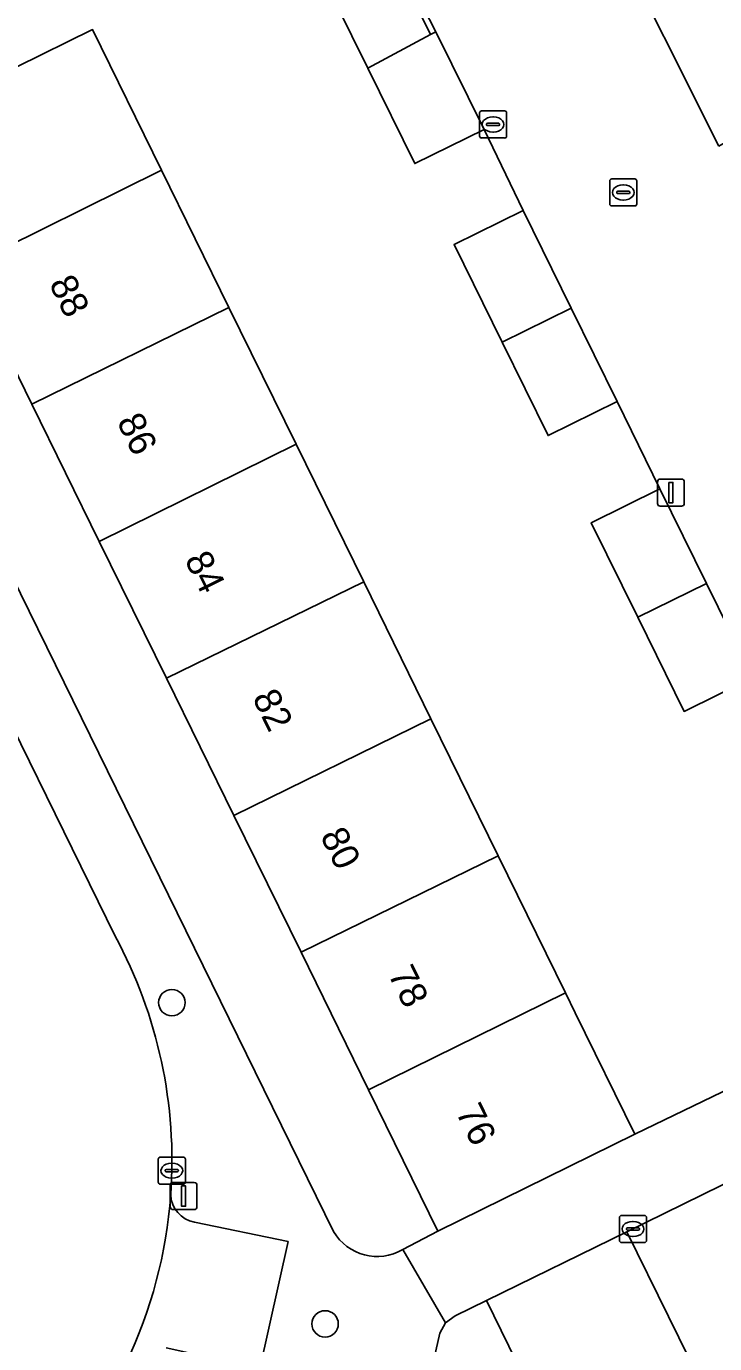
# Model space of a CAD drawing. Extents: x 159716 to 160783, y 383290 to 384031.
# Drawn here: x 160086.41 to 160111.85, y 383383.96 to 383432.64 of the extents above; entities that cross this region are included whole.
import ezdxf

# ---------------------------------------------------------------- set-up
doc = ezdxf.new("R2010")
doc.units = 0
for name, color, linetype in [('IMGEO_Boom', 7, 'Continuous'), ('IMGEO_Erf', 7, 'Continuous'), ('IMGEO_Kolk', 7, 'Continuous'), ('IMGEO_Lichtmast', 7, 'Continuous'), ('IMGEO_Pand', 7, 'Continuous'), ('IMGEO_Pand_nummerreeks', 7, 'Continuous'), ('IMGEO_Parkeervlak_open', 7, 'Continuous'), ('IMGEO_Rijbaan_lokaal_open', 7, 'Continuous'), ('IMGEO_Voetpad_open', 7, 'Continuous')]:
    doc.layers.add(name, color=color, linetype=linetype)

msp = doc.modelspace()

# ---------------------------------------------------------------- linework, layer by layer
at = {"layer": 'IMGEO_Boom'}
for centre in [(160091.79, 383396.564), (160097.452, 383384.694)]:
    msp.add_circle(centre, 0.489, dxfattribs=at)
at = {"layer": 'IMGEO_Erf'}
for points in [[(160099.795, 383435.475), (160101.344, 383432.33), (160101.55, 383432.432), (160099.933, 383435.581)], [(160103.996, 383420.964), (160102.218, 383424.571), (160104.772, 383425.829), (160103.329, 383428.824), (160100.768, 383427.562), (160099.034, 383431.087), (160097.261, 383434.69)], [(160100.324, 383387.443), (160101.622, 383388.127), (160099.062, 383393.337), (160096.563, 383398.425), (160094.082, 383403.475), (160091.588, 383408.552), (160089.107, 383413.603), (160086.617, 383418.672), (160084.135, 383423.723), (160081.575, 383428.935), (160086.063, 383431.14), (160088.858, 383432.513), (160091.41, 383427.319), (160093.9, 383422.25), (160096.381, 383417.199), (160098.879, 383412.113), (160101.365, 383407.053), (160103.85, 383401.994), (160106.34, 383396.925), (160106.7, 383396.193), (160108.905, 383391.705), (160116.095, 383395.177)], [(160080.405, 383423.453), (160097.768, 383388.109)], [(160113.264, 383408.578), (160110.723, 383407.326), (160109.007, 383410.807), (160107.289, 383414.292), (160109.83, 383415.544), (160108.251, 383418.772), (160105.697, 383417.513), (160103.996, 383420.964)], [(160106.151, 383379.966), (160103.414, 383385.561), (160102.265, 383384.994), (160101.907, 383384.734), (160101.689, 383384.35), (160090.51, 383335.068)]]:
    msp.add_lwpolyline(points, dxfattribs=at)
msp.add_lwpolyline([(160120.499, 383393.934), (160108.611, 383388.092), (160111.681, 383381.843), (160115.082, 383383.587), (160123.539, 383387.742)], close=True, dxfattribs=at)
msp.add_arc((160099.379, 383389.055), 1.869, 210.4205, 300.3706, dxfattribs=at)
at = {"layer": 'IMGEO_Kolk'}
for p, q in [((160103.161, 383428.584), (160103.161, 383429.436)), ((160103.236, 383429.51), (160104.088, 383429.51)), ((160103.649, 383429.29), (160103.674, 383429.29)), ((160104.162, 383429.436), (160104.162, 383428.584)), ((160103.42, 383429.004), (160103.42, 383429.016)), ((160103.858, 383428.967), (160103.46, 383428.967)), ((160103.463, 383429.053), (160103.861, 383429.053)), ((160103.904, 383429.016), (160103.904, 383429.004)), ((160104.088, 383428.51), (160103.236, 383428.51)), ((160103.672, 383428.73), (160103.647, 383428.73)), ((160107.973, 383426.072), (160107.973, 383426.924)), ((160108.048, 383426.998), (160108.9, 383426.998)), ((160108.974, 383426.924), (160108.974, 383426.072)), ((160108.232, 383426.492), (160108.232, 383426.504)), ((160108.67, 383426.455), (160108.272, 383426.455)), ((160108.275, 383426.541), (160108.673, 383426.541)), ((160108.461, 383426.778), (160108.486, 383426.778)), ((160108.716, 383426.504), (160108.716, 383426.492)), ((160108.9, 383425.998), (160108.048, 383425.998)), ((160108.484, 383426.218), (160108.459, 383426.218)), ((160091.362, 383390.856), (160092.214, 383390.856)), ((160091.287, 383389.93), (160091.287, 383390.782)), ((160091.546, 383390.35), (160091.546, 383390.362)), ((160091.589, 383390.399), (160091.987, 383390.399)), ((160091.775, 383390.636), (160091.8, 383390.636)), ((160092.03, 383390.362), (160092.03, 383390.35)), ((160092.288, 383390.782), (160092.288, 383389.93)), ((160092.214, 383389.856), (160091.362, 383389.856)), ((160091.984, 383390.313), (160091.586, 383390.313)), ((160091.798, 383390.076), (160091.773, 383390.076)), ((160108.332, 383387.775), (160108.332, 383388.627)), ((160108.407, 383388.701), (160109.259, 383388.701)), ((160108.82, 383388.481), (160108.845, 383388.481)), ((160109.333, 383388.627), (160109.333, 383387.775)), ((160108.591, 383388.195), (160108.591, 383388.207)), ((160109.029, 383388.158), (160108.631, 383388.158)), ((160108.634, 383388.244), (160109.032, 383388.244)), ((160108.843, 383387.921), (160108.818, 383387.921)), ((160109.075, 383388.207), (160109.075, 383388.195)), ((160109.259, 383387.701), (160108.407, 383387.701))]:
    msp.add_line(p, q, dxfattribs=at)
for points in [[(160103.161, 383428.584), (160103.161, 383429.436)], [(160103.236, 383429.51), (160104.088, 383429.51)], [(160104.162, 383429.436), (160104.162, 383428.584)], [(160104.088, 383428.51), (160103.236, 383428.51)], [(160107.973, 383426.072), (160107.973, 383426.924)], [(160108.048, 383426.998), (160108.9, 383426.998)], [(160108.974, 383426.924), (160108.974, 383426.072)], [(160108.9, 383425.998), (160108.048, 383425.998)], [(160091.362, 383390.856), (160092.214, 383390.856)], [(160091.287, 383389.93), (160091.287, 383390.782)], [(160092.288, 383390.782), (160092.288, 383389.93)], [(160092.214, 383389.856), (160091.362, 383389.856)], [(160108.332, 383387.775), (160108.332, 383388.627)], [(160108.407, 383388.701), (160109.259, 383388.701)], [(160109.333, 383388.627), (160109.333, 383387.775)], [(160109.259, 383387.701), (160108.407, 383387.701)]]:
    msp.add_lwpolyline(points, dxfattribs=at)
for centre, radius, start, end in [((160103.238, 383429.434), 0.0765, 91.552, 178.448), ((160103.238, 383429.434), 0.0765, 91.552, 178.448), ((160104.086, 383429.434), 0.0765, 1.552, 88.448), ((160104.086, 383429.434), 0.0765, 1.552, 88.448), ((160103.46, 383429.013), 0.0403, 85.8775, 175.7526), ((160103.457, 383429.003), 0.0366, 178.938, 274.7102), ((160103.861, 383429.01), 0.043, 264.8664, 352.4533), ((160103.865, 383429.015), 0.0386, 1.7309, 96.639), ((160103.238, 383428.586), 0.0765, 181.552, 268.448), ((160103.238, 383428.586), 0.0765, 181.552, 268.448), ((160104.086, 383428.586), 0.0765, 271.552, 358.448), ((160104.086, 383428.586), 0.0765, 271.552, 358.448), ((160108.05, 383426.922), 0.0765, 91.552, 178.448), ((160108.05, 383426.922), 0.0765, 91.552, 178.448), ((160108.898, 383426.922), 0.0765, 1.552, 88.448), ((160108.898, 383426.922), 0.0765, 1.552, 88.448), ((160108.272, 383426.501), 0.0403, 85.8775, 175.7526), ((160108.269, 383426.491), 0.0366, 178.938, 274.7102), ((160108.673, 383426.498), 0.043, 264.8664, 352.4533), ((160108.677, 383426.503), 0.0386, 1.7309, 96.639), ((160108.05, 383426.074), 0.0765, 181.552, 268.448), ((160108.05, 383426.074), 0.0765, 181.552, 268.448), ((160108.898, 383426.074), 0.0765, 271.552, 358.448), ((160108.898, 383426.074), 0.0765, 271.552, 358.448), ((160091.364, 383390.78), 0.0765, 91.552, 178.448), ((160091.364, 383390.78), 0.0765, 91.552, 178.448), ((160092.212, 383390.78), 0.0765, 1.552, 88.448), ((160092.212, 383390.78), 0.0765, 1.552, 88.448), ((160091.586, 383390.359), 0.0403, 85.8775, 175.7526), ((160091.583, 383390.349), 0.0366, 178.938, 274.7102), ((160091.987, 383390.356), 0.043, 264.8664, 352.4533), ((160091.991, 383390.361), 0.0386, 1.7309, 96.639), ((160091.364, 383389.932), 0.0765, 181.552, 268.448), ((160091.364, 383389.932), 0.0765, 181.552, 268.448), ((160092.212, 383389.932), 0.0765, 271.552, 358.448), ((160092.212, 383389.932), 0.0765, 271.552, 358.448), ((160108.409, 383388.625), 0.0765, 91.552, 178.448), ((160108.409, 383388.625), 0.0765, 91.552, 178.448), ((160109.257, 383388.625), 0.0765, 1.552, 88.448), ((160109.257, 383388.625), 0.0765, 1.552, 88.448), ((160108.631, 383388.204), 0.0403, 85.8775, 175.7526), ((160108.628, 383388.194), 0.0366, 178.938, 274.7102), ((160109.032, 383388.201), 0.043, 264.8664, 352.4533), ((160109.036, 383388.206), 0.0386, 1.7309, 96.639), ((160108.409, 383387.777), 0.0765, 181.552, 268.448), ((160108.409, 383387.777), 0.0765, 181.552, 268.448), ((160109.257, 383387.777), 0.0765, 271.552, 358.448), ((160109.257, 383387.777), 0.0765, 271.552, 358.448)]:
    msp.add_arc(centre, radius, start, end, dxfattribs=at)
for centre, major_axis, ratio, start_param, end_param in [((160103.648, 383429.01), (-0.387, 0.002), 0.722429, 4.712389, 7.853982), ((160103.673, 383429.01), (-0.39, 0.002), 0.717154, 1.570796, 4.712389), ((160108.46, 383426.498), (-0.387, 0.002), 0.722429, 4.712389, 7.853982), ((160108.485, 383426.498), (-0.39, 0.002), 0.717154, 1.570796, 4.712389), ((160091.774, 383390.356), (-0.387, 0.002), 0.722429, 4.712389, 7.853982), ((160091.799, 383390.356), (-0.39, 0.002), 0.717154, 1.570796, 4.712389), ((160108.819, 383388.201), (-0.387, 0.002), 0.722429, 4.712389, 7.853982), ((160108.844, 383388.201), (-0.39, 0.002), 0.717154, 1.570796, 4.712389)]:
    msp.add_ellipse(centre, major_axis=major_axis, ratio=ratio, start_param=start_param, end_param=end_param, dxfattribs=at)
at = {"layer": 'IMGEO_Lichtmast'}
for p, q in [((160109.738, 383415.008), (160109.738, 383415.808)), ((160109.738, 383415.808), (160109.738, 383415.008)), ((160109.838, 383415.908), (160110.628, 383415.908)), ((160110.628, 383415.908), (160109.838, 383415.908)), ((160110.728, 383415.808), (160110.728, 383415.008)), ((160110.728, 383415.008), (160110.728, 383415.808)), ((160110.628, 383414.908), (160109.838, 383414.908)), ((160109.838, 383414.908), (160110.628, 383414.908)), ((160091.828, 383389.919), (160092.618, 383389.919)), ((160092.618, 383389.919), (160091.828, 383389.919)), ((160091.728, 383389.019), (160091.728, 383389.819)), ((160091.728, 383389.819), (160091.728, 383389.019)), ((160092.718, 383389.819), (160092.718, 383389.019)), ((160092.718, 383389.019), (160092.718, 383389.819)), ((160092.618, 383388.919), (160091.828, 383388.919)), ((160091.828, 383388.919), (160092.618, 383388.919))]:
    msp.add_line(p, q, dxfattribs=at)
for points in [[(160110.158, 383415.783), (160110.308, 383415.783), (160110.308, 383415.033), (160110.158, 383415.033), (160110.158, 383415.783)], [(160092.148, 383389.794), (160092.298, 383389.794), (160092.298, 383389.044), (160092.148, 383389.044), (160092.148, 383389.794)]]:
    msp.add_lwpolyline(points, dxfattribs=at)
for centre, start, end in [((160109.838, 383415.808), 90, 180), ((160109.838, 383415.808), 90, 180), ((160110.628, 383415.808), 0, 90), ((160110.628, 383415.808), 360, 90), ((160109.838, 383415.008), 180, 270), ((160109.838, 383415.008), 180, 270), ((160110.628, 383415.008), 270, 0), ((160110.628, 383415.008), 270, 0), ((160091.828, 383389.819), 90, 180), ((160091.828, 383389.819), 90, 180), ((160092.618, 383389.819), 0, 90), ((160092.618, 383389.819), 360, 90), ((160091.828, 383389.019), 180, 270), ((160091.828, 383389.019), 180, 270), ((160092.618, 383389.019), 270, 0), ((160092.618, 383389.019), 270, 0)]:
    msp.add_arc(centre, 0.1, start, end, dxfattribs=at)
at = {"layer": 'IMGEO_Pand'}
for points in [[(160112.006, 383428.209), (160116.849, 383431.044), (160114.078, 383435.99), (160116.287, 383437.29), (160114.61, 383440.211), (160107.952, 383436.294)], [(160101.344, 383432.33), (160099.795, 383435.475), (160099.611, 383435.848), (160097.261, 383434.69), (160099.034, 383431.087)], [(160084.135, 383423.723), (160091.41, 383427.319), (160088.858, 383432.513), (160086.063, 383431.14), (160081.575, 383428.935)], [(160101.344, 383432.33), (160099.034, 383431.087), (160100.768, 383427.562), (160103.329, 383428.824), (160101.55, 383432.432)], [(160093.9, 383422.25), (160091.41, 383427.319), (160084.135, 383423.723), (160086.617, 383418.672)], [(160106.549, 383422.225), (160104.772, 383425.829), (160102.218, 383424.571), (160103.996, 383420.964)], [(160093.9, 383422.25), (160086.617, 383418.672), (160089.107, 383413.603), (160096.381, 383417.199)], [(160106.549, 383422.225), (160103.996, 383420.964), (160105.697, 383417.513), (160108.251, 383418.772)], [(160091.588, 383408.552), (160098.879, 383412.113), (160096.381, 383417.199), (160089.107, 383413.603)], [(160109.007, 383410.807), (160111.549, 383412.056), (160109.83, 383415.544), (160107.289, 383414.292)], [(160091.588, 383408.552), (160094.082, 383403.475), (160101.365, 383407.053), (160098.879, 383412.113)], [(160109.007, 383410.807), (160110.723, 383407.326), (160113.264, 383408.578), (160111.549, 383412.056)], [(160096.563, 383398.425), (160103.85, 383401.994), (160101.365, 383407.053), (160094.082, 383403.475)], [(160106.34, 383396.925), (160103.85, 383401.994), (160096.563, 383398.425), (160099.062, 383393.337)], [(160106.34, 383396.925), (160099.062, 383393.337), (160101.622, 383388.127), (160108.905, 383391.705), (160106.7, 383396.193)], [(160112.166, 383380.855), (160111.681, 383381.843), (160108.611, 383388.092), (160103.414, 383385.561), (160106.151, 383379.966), (160105.997, 383379.281), (160105.155, 383379.463), (160103.679, 383379.782), (160102.796, 383375.896), (160104.283, 383375.575), (160103.88, 383373.779), (160111.722, 383372.021), (160111.711, 383371.972), (160114.65, 383371.313), (160115.937, 383377.06), (160113, 383377.718), (160111.536, 383378.046)]]:
    msp.add_lwpolyline(points, close=True, dxfattribs=at)
at = {"layer": 'IMGEO_Parkeervlak_open'}
msp.add_lwpolyline([(160091.579, 383383.811), (160095.046, 383383.051), (160096.086, 383387.736), (160092.62, 383388.458)], dxfattribs=at)
for centre, radius, start, end in [((160074.375, 383390.738), 17.417, 334.5514, 355.7916), ((160092.81, 383389.507), 1.066, 182.5444, 259.714)]:
    msp.add_arc(centre, radius, start, end, dxfattribs=at)
at = {"layer": 'IMGEO_Rijbaan_lokaal_open'}
for points in [[(160112.006, 383428.209), (160107.952, 383436.294)], [(160099.933, 383435.581), (160101.55, 383432.432), (160103.329, 383428.824), (160104.772, 383425.829), (160106.549, 383422.225), (160108.251, 383418.772), (160109.83, 383415.544), (160111.549, 383412.056), (160113.264, 383408.578)], [(160089.692, 383399.019), (160078.272, 383422.273), (160077.081, 383424.063)]]:
    msp.add_lwpolyline(points, dxfattribs=at)
for centre, radius, start, end in [((160074.401, 383390.735), 17.391, 355.7961, 28.4467), ((160074.375, 383390.738), 17.417, 334.5514, 355.7916)]:
    msp.add_arc(centre, radius, start, end, dxfattribs=at)
at = {"layer": 'IMGEO_Voetpad_open'}
for points in [[(160069.173, 383429.702), (160072.625, 383427.835), (160074.442, 383426.665), (160074.767, 383427.04), (160077.431, 383424.419), (160077.081, 383424.063), (160078.272, 383422.273), (160089.692, 383399.019)], [(160097.768, 383388.109), (160080.405, 383423.453)], [(160092.62, 383388.458), (160096.086, 383387.736), (160095.046, 383383.051), (160091.579, 383383.811)], [(160101.689, 383384.35), (160101.907, 383384.734), (160100.324, 383387.443)], [(160087.089, 383367.439), (160092.382, 383366.266), (160088.524, 383349.303), (160083.139, 383350.541), (160082.957, 383349.761), (160082.606, 383348.26), (160084.319, 383348.085), (160084.347, 383334.777), (160088.414, 383334.739), (160088.391, 383334.948), (160090.51, 383335.068), (160101.689, 383384.35)]]:
    msp.add_lwpolyline(points, dxfattribs=at)
msp.add_lwpolyline([(160120.499, 383393.934), (160119.169, 383396.693), (160116.095, 383395.177), (160108.905, 383391.705), (160101.622, 383388.127), (160100.324, 383387.443), (160101.907, 383384.734), (160102.265, 383384.994), (160103.414, 383385.561), (160108.611, 383388.092)], close=True, dxfattribs=at)
for centre, radius, start, end in [((160074.401, 383390.735), 17.391, 355.7961, 28.4467), ((160092.81, 383389.507), 1.066, 182.5444, 259.714), ((160099.379, 383389.055), 1.869, 210.4205, 300.3706)]:
    msp.add_arc(centre, radius, start, end, dxfattribs=at)

# ---------------------------------------------------------------- texts
at = {"layer": 'IMGEO_Pand_nummerreeks'}
for s, p in [('88', (160087.233, 383423.133)), ('86', (160089.738, 383418.035)), ('84', (160092.243, 383412.934)), ('82', (160094.747, 383407.836)), ('80', (160097.256, 383402.729)), ('78', (160099.762, 383397.628)), ('76', (160102.267, 383392.53))]:
    msp.add_text(s, height=1, rotation=296.1627, dxfattribs=at).set_placement(p)

doc.saveas('drawing.dxf')
